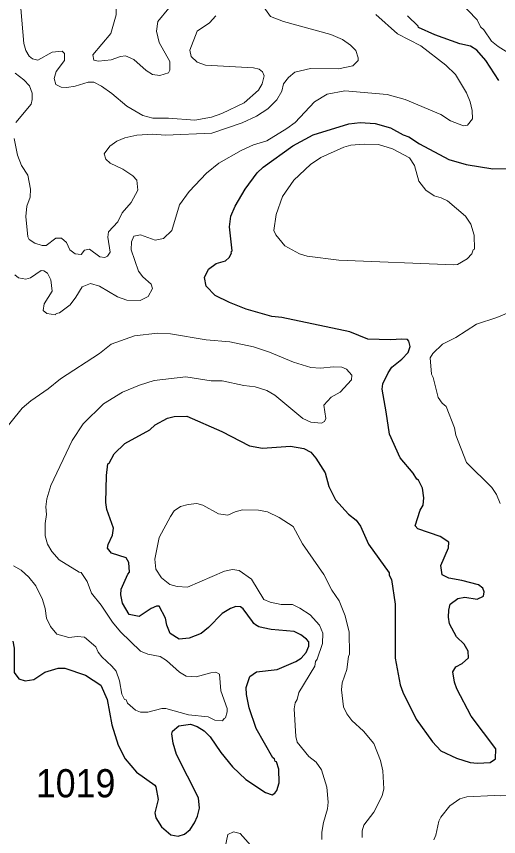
# Model space of a CAD drawing. Extents: x 447.8 to 473.9, y 7733.1 to 7760.8.
# Drawn here: x 462.281 to 463.651, y 7748.146 to 7750.473 of the extents above; entities that cross this region are included whole.
import ezdxf

# ---------------------------------------------------------------- set-up
doc = ezdxf.new("R2010")
doc.units = 0
doc.header["$LTSCALE"] = 0.032
doc.layers.add('1', color=7, linetype='Continuous', lineweight=25)
doc.layers.add('2', color=7, linetype='Continuous', lineweight=13)
doc.layers.add('21', color=7, linetype='Continuous')

msp = doc.modelspace()

# ---------------------------------------------------------------- linework, layer by layer
at = {"layer": '1'}
for points in [[(463.6509, 7750.2912), (463.6143, 7750.3483), (463.5893, 7750.3768), (463.5705, 7750.3882), (463.541, 7750.3949), (463.4695, 7750.4203), (463.4234, 7750.4418), (463.4227, 7750.4453), (463.3923, 7750.4742)], [(462.8155, 7749.732), (462.8269, 7749.756), (462.8487, 7749.7719), (462.8748, 7749.7799), (462.8859, 7749.7895), (462.8919, 7749.8013), (462.8911, 7749.8055), (462.8939, 7749.8083), (462.8861, 7749.8765), (462.8903, 7749.9065), (462.903, 7749.9348), (462.9314, 7749.9825), (462.9652, 7750.0295), (462.9818, 7750.0453), (463.0668, 7750.1061), (463.1241, 7750.137), (463.2251, 7750.1685), (463.258, 7750.1719), (463.3004, 7750.1693), (463.3437, 7750.1574), (463.3794, 7750.1375), (463.3958, 7750.1317), (463.426, 7750.1119), (463.5093, 7750.067), (463.5586, 7750.0526), (463.634, 7750.0404), (463.6953, 7750.0419)], [(463.007, 7749.6218), (462.9334, 7749.643), (462.8862, 7749.6616), (462.8461, 7749.6817), (462.8204, 7749.7076), (462.8155, 7749.732)], [(462.5373, 7749.1711), (462.5412, 7749.2036), (462.5446, 7749.2055), (462.5586, 7749.2326), (462.5892, 7749.2618), (462.6602, 7749.3005), (462.6758, 7749.3147), (462.7107, 7749.3331), (462.729, 7749.3378), (462.7653, 7749.3389), (462.8648, 7749.2951), (462.9436, 7749.2545), (462.9803, 7749.2485), (463.0595, 7749.254), (463.0976, 7749.2476), (463.1174, 7749.2365), (463.1319, 7749.2198), (463.1581, 7749.1786), (463.1683, 7749.1391), (463.1873, 7749.1013), (463.2243, 7749.0607), (463.2461, 7749.0443), (463.2585, 7749.0266), (463.2808, 7748.9763), (463.3396, 7748.8949), (463.34, 7748.8875), (463.3461, 7748.8756), (463.3573, 7748.8059), (463.3573, 7748.6528), (463.3714, 7748.5766), (463.3789, 7748.5558), (463.4165, 7748.4792), (463.4633, 7748.4155), (463.4868, 7748.3901), (463.5308, 7748.3689), (463.5697, 7748.3569), (463.5908, 7748.3547), (463.6263, 7748.357), (463.6419, 7748.367), (463.6426, 7748.3953), (463.5726, 7748.4878), (463.5322, 7748.5651), (463.5251, 7748.584), (463.5211, 7748.6133), (463.529, 7748.628), (463.5468, 7748.6371), (463.5656, 7748.653), (463.5642, 7748.672), (463.5529, 7748.6921), (463.5313, 7748.7127), (463.5114, 7748.7495), (463.5081, 7748.7687), (463.5089, 7748.7883), (463.5132, 7748.8053), (463.5351, 7748.8217), (463.5545, 7748.8251), (463.5895, 7748.8196), (463.6082, 7748.8287), (463.6096, 7748.8403), (463.6057, 7748.8508), (463.5938, 7748.8603), (463.5465, 7748.8732), (463.5095, 7748.8792), (463.4907, 7748.8891), (463.4864, 7748.9157), (463.5085, 7748.9655), (463.5095, 7748.9814), (463.485, 7748.9978), (463.4215, 7749.0196), (463.4139, 7749.0282), (463.4277, 7749.0724), (463.4368, 7749.0863), (463.4383, 7749.107), (463.435, 7749.1346), (463.4229, 7749.1577), (463.4184, 7749.1603), (463.408, 7749.1769), (463.3711, 7749.2209), (463.341, 7749.2883), (463.3316, 7749.351), (463.3197, 7749.4155), (463.322, 7749.4308), (463.3367, 7749.4619), (463.3478, 7749.4783), (463.376, 7749.5003), (463.3939, 7749.5198), (463.3997, 7749.5369), (463.3958, 7749.5522), (463.3922, 7749.5562), (463.3757, 7749.5578), (463.3433, 7749.5555), (463.2791, 7749.5578), (463.2279, 7749.5787), (463.0351, 7749.6187), (463.007, 7749.6218)], [(462.5415, 7748.9753), (462.554, 7749.0012), (462.5574, 7749.021), (462.5386, 7749.0738), (462.535, 7749.0942), (462.5373, 7749.1711)], [(462.331, 7748.5919), (462.3618, 7748.6127), (462.4002, 7748.6239), (462.4192, 7748.6239), (462.4772, 7748.6039), (462.521, 7748.5761), (462.5391, 7748.5354), (462.5527, 7748.4636), (462.5708, 7748.4053), (462.5904, 7748.3669), (462.6221, 7748.3293), (462.6741, 7748.2923), (462.6776, 7748.2873), (462.6839, 7748.252), (462.6745, 7748.2136), (462.6777, 7748.1995), (462.6937, 7748.1744), (462.7201, 7748.1511), (462.7409, 7748.1473), (462.7585, 7748.1535), (462.7748, 7748.1665), (462.7874, 7748.1856), (462.7958, 7748.2047), (462.801, 7748.2273), (462.7983, 7748.2566), (462.736, 7748.3797), (462.7261, 7748.4111), (462.7225, 7748.438), (462.7245, 7748.4458), (462.7423, 7748.461), (462.7758, 7748.4651), (462.7946, 7748.4588), (462.8141, 7748.4466), (462.8319, 7748.4292), (462.8621, 7748.3847), (462.8954, 7748.3445), (462.9328, 7748.3087), (462.989, 7748.2719), (463.0075, 7748.2651), (463.0154, 7748.2693), (463.0209, 7748.277), (463.0278, 7748.2993), (463.0263, 7748.3375), (463.0203, 7748.3586), (463.016, 7748.3596), (463.0141, 7748.3673), (463.0097, 7748.3699), (462.9623, 7748.4529), (462.9421, 7748.5113), (462.935, 7748.5491), (462.9342, 7748.569), (462.944, 7748.6001), (462.9627, 7748.6141), (463.0214, 7748.6202), (463.0744, 7748.6429), (463.0898, 7748.6524), (463.1039, 7748.6687), (463.1117, 7748.6865), (463.1119, 7748.6985), (463.1048, 7748.7063), (463.0893, 7748.719), (463.07, 7748.7282), (463.005, 7748.7338), (462.9821, 7748.7385), (462.9696, 7748.7413), (462.9599, 7748.7474), (462.9556, 7748.7505), (462.9516, 7748.7566), (462.925, 7748.7925), (462.9177, 7748.7979), (462.9049, 7748.7987), (462.8897, 7748.7937), (462.8652, 7748.7794), (462.8264, 7748.7392), (462.8063, 7748.7224), (462.7722, 7748.7097), (462.7439, 7748.7065), (462.7184, 7748.7229), (462.709, 7748.7463), (462.7047, 7748.7662), (462.6869, 7748.8002), (462.6796, 7748.8003), (462.6645, 7748.7937), (462.6295, 7748.7708), (462.6016, 7748.7764), (462.5827, 7748.8083), (462.5782, 7748.8324), (462.5784, 7748.848), (462.5974, 7748.8907), (462.6021, 7748.8961), (462.6006, 7748.9242), (462.5929, 7748.9369), (462.5513, 7748.9502), (462.5399, 7748.965), (462.5415, 7748.9753)], [(462.2714, 7748.7009), (462.2752, 7748.6809), (462.2751, 7748.6115), (462.2881, 7748.5936), (462.3064, 7748.588), (462.331, 7748.5919)]]:
    msp.add_lwpolyline(points, dxfattribs=at)
at = {"layer": '2'}
for points in [[(462.5438, 7750.6136), (462.5633, 7750.5965), (462.5715, 7750.5775), (462.5638, 7750.5147), (462.5651, 7750.4775), (462.5494, 7750.4242)], [(463.727, 7750.3396), (463.6497, 7750.3876), (463.6306, 7750.4029), (463.609, 7750.4347), (463.5995, 7750.443), (463.5898, 7750.4637), (463.5102, 7750.5463)], [(462.8477, 7750.475), (462.8299, 7750.4549), (462.7943, 7750.4309), (462.7739, 7750.3774), (462.778, 7750.3589), (462.7949, 7750.3432), (462.8182, 7750.3343), (462.9549, 7750.3273), (462.9712, 7750.3234), (462.98, 7750.3157), (462.9846, 7750.3041), (462.9794, 7750.2819), (462.9693, 7750.2635), (462.928, 7750.2281), (462.8645, 7750.1972), (462.8353, 7750.1876), (462.7885, 7750.1791), (462.7134, 7750.1846), (462.6692, 7750.1847), (462.6401, 7750.1921), (462.5953, 7750.218), (462.5523, 7750.2546), (462.5231, 7750.2748), (462.5009, 7750.2864), (462.4856, 7750.2867), (462.4486, 7750.2753), (462.4249, 7750.2713), (462.4085, 7750.272), (462.3936, 7750.2799), (462.3883, 7750.2971), (462.3942, 7750.3166), (462.4176, 7750.3478), (462.4177, 7750.3674), (462.4113, 7750.3745), (462.3829, 7750.3715), (462.342, 7750.3489), (462.3273, 7750.3526), (462.318, 7750.3605), (462.3079, 7750.3759), (462.3021, 7750.3964), (462.2912, 7750.5293)], [(462.9844, 7750.4995), (463.0033, 7750.4725), (463.0402, 7750.4587), (463.1742, 7750.422), (463.2076, 7750.4071), (463.2301, 7750.3919), (463.245, 7750.376), (463.2515, 7750.3559), (463.2515, 7750.3477), (463.2371, 7750.3331), (463.1961, 7750.3242), (463.1165, 7750.3257), (463.072, 7750.3145), (463.0541, 7750.2999), (463.04, 7750.282), (463.0355, 7750.2611), (463.0206, 7750.2366), (462.9958, 7750.2112), (462.9636, 7750.1905), (462.9222, 7750.1716), (462.8363, 7750.1414), (462.7043, 7750.1365), (462.6679, 7750.1389), (462.6231, 7750.1365), (462.5891, 7750.1284), (462.567, 7750.1189), (462.5464, 7750.1047), (462.5302, 7750.0835), (462.5353, 7750.068), (462.548, 7750.0571), (462.5833, 7750.0394), (462.6123, 7750.0207), (462.6232, 7750.0085), (462.6263, 7749.9798), (462.6073, 7749.9448), (462.5816, 7749.9156), (462.5694, 7749.8906), (462.543, 7749.862), (462.5406, 7749.8464), (462.5478, 7749.8046), (462.5404, 7749.7929), (462.5322, 7749.7895), (462.5186, 7749.7909), (462.4886, 7749.8126), (462.4744, 7749.8096), (462.4653, 7749.7979), (462.4486, 7749.7996), (462.4327, 7749.8109), (462.4238, 7749.8315), (462.4094, 7749.844), (462.3929, 7749.8439), (462.3662, 7749.8236), (462.3546, 7749.8232), (462.3334, 7749.8297), (462.3173, 7749.8404), (462.3137, 7749.848), (462.3081, 7749.9053), (462.3114, 7749.9351), (462.3202, 7749.9606), (462.3217, 7749.983), (462.3136, 7750.0224), (462.2959, 7750.0503), (462.284, 7750.0791), (462.2753, 7750.1263)], [(462.5494, 7750.4242), (462.4985, 7750.3637), (462.5015, 7750.3492), (462.5142, 7750.3458), (462.5502, 7750.3502), (462.5766, 7750.3593), (462.5914, 7750.3608), (462.6149, 7750.3504), (462.6495, 7750.3192), (462.6679, 7750.3086), (462.6887, 7750.3051), (462.7128, 7750.3132), (462.7175, 7750.3208), (462.7175, 7750.345), (462.687, 7750.3994), (462.6793, 7750.4307), (462.6834, 7750.4587), (462.7141, 7750.4968)], [(462.2771, 7749.7404), (462.2876, 7749.7315), (462.3085, 7749.7278), (462.3212, 7749.7315), (462.3516, 7749.7518), (462.359, 7749.7517), (462.3695, 7749.7447), (462.3794, 7749.7261), (462.3826, 7749.6937), (462.3603, 7749.6575), (462.357, 7749.6384), (462.3675, 7749.6302), (462.3927, 7749.6268), (462.394, 7749.6298), (462.4039, 7749.6324), (462.4336, 7749.6546), (462.4505, 7749.6762), (462.4678, 7749.7062), (462.4917, 7749.7149), (462.5175, 7749.7076), (462.5688, 7749.6779), (462.5949, 7749.6683), (462.6327, 7749.6669), (462.6553, 7749.6783), (462.6677, 7749.7009), (462.6638, 7749.7133), (462.6405, 7749.7344), (462.6285, 7749.7504), (462.6071, 7749.8112), (462.6078, 7749.8332), (462.6145, 7749.8498), (462.634, 7749.8536), (462.6757, 7749.8384), (462.6994, 7749.843), (462.7226, 7749.8655), (462.7444, 7749.9381), (462.7719, 7749.976), (462.8215, 7750.0283), (462.8566, 7750.0566), (462.9194, 7750.0926), (462.9543, 7750.1091), (462.9923, 7750.1204), (463.0497, 7750.1546), (463.0732, 7750.1722), (463.1278, 7750.2309), (463.164, 7750.2525), (463.2136, 7750.2617), (463.334, 7750.2519), (463.3853, 7750.2373), (463.4869, 7750.1944), (463.514, 7750.1768), (463.551, 7750.1623), (463.5622, 7750.1645), (463.5768, 7750.1826), (463.5752, 7750.2062), (463.5698, 7750.2308), (463.5597, 7750.2562), (463.5278, 7750.3084), (463.5011, 7750.3351), (463.4299, 7750.3892), (463.3639, 7750.424), (463.3017, 7750.4787)], [(462.2801, 7750.1725), (462.3233, 7750.2241), (462.3265, 7750.2376), (462.3259, 7750.2552), (462.3184, 7750.276), (462.3027, 7750.2934), (462.2778, 7750.3117)], [(463.6554, 7749.0913), (463.6443, 7749.1169), (463.6312, 7749.1365), (463.5598, 7749.2077), (463.529, 7749.2851), (463.5253, 7749.3056), (463.5017, 7749.3667), (463.4903, 7749.376), (463.4793, 7749.392), (463.4647, 7749.4488), (463.46, 7749.4585), (463.4568, 7749.5046), (463.4635, 7749.5165), (463.4915, 7749.543), (463.529, 7749.5624), (463.588, 7749.5997), (463.6453, 7749.6193), (463.7206, 7749.6505)], [(462.8259, 7748.4863), (462.8448, 7748.4762), (462.8668, 7748.4743), (462.8712, 7748.4817), (462.8753, 7748.4832), (462.8803, 7748.4999), (462.8796, 7748.5093), (462.862, 7748.5603), (462.8582, 7748.6067), (462.8476, 7748.6126), (462.8331, 7748.6111), (462.7919, 7748.5996), (462.7638, 7748.601), (462.7443, 7748.6124), (462.7075, 7748.6462), (462.69, 7748.6574), (462.6542, 7748.6639), (462.6342, 7748.6723), (462.5769, 7748.7271), (462.5539, 7748.7549), (462.5219, 7748.803), (462.4947, 7748.8367), (462.4819, 7748.8703), (462.4648, 7748.8959), (462.4593, 7748.8968), (462.4029, 7748.931), (462.382, 7748.9548), (462.3695, 7748.9763), (462.3634, 7748.9996), (462.3634, 7749.0348), (462.3666, 7749.0605), (462.365, 7749.0814), (462.3682, 7749.1041), (462.3794, 7749.1423), (462.44, 7749.2702), (462.471, 7749.3176), (462.5288, 7749.3736), (462.583, 7749.4071), (462.6305, 7749.4273), (462.6729, 7749.44), (462.7629, 7749.4504), (462.834, 7749.4393), (462.8656, 7749.4392), (462.9273, 7749.4261), (462.9594, 7749.4224), (462.9928, 7749.4122), (463.0148, 7749.3982), (463.0947, 7749.3324), (463.1175, 7749.322), (463.1478, 7749.319), (463.1565, 7749.3243), (463.1601, 7749.3321), (463.154, 7749.3701), (463.1755, 7749.393), (463.2004, 7749.4067), (463.2331, 7749.4419), (463.2339, 7749.4549), (463.2189, 7749.4726), (463.2057, 7749.4784), (463.1819, 7749.4792), (463.1448, 7749.4753), (463.1172, 7749.4771), (463.0678, 7749.4919), (463.0001, 7749.5208), (462.9546, 7749.5354), (462.8873, 7749.5499), (462.8202, 7749.5554), (462.7192, 7749.5722), (462.682, 7749.5746), (462.617, 7749.5667), (462.5508, 7749.5433), (462.5175, 7749.5171), (462.4066, 7749.4448), (462.3716, 7749.4163), (462.3223, 7749.3827), (462.2975, 7749.3613), (462.2393, 7749.2887)], [(463.1488, 7748.1384), (463.149, 7748.1588), (463.1538, 7748.1864), (463.165, 7748.2247), (463.1665, 7748.2439), (463.1633, 7748.2865), (463.1481, 7748.3362), (463.1326, 7748.3578), (463.112, 7748.3731), (463.0785, 7748.414), (463.0752, 7748.4305), (463.0704, 7748.5084), (463.0728, 7748.5257), (463.0783, 7748.5354), (463.0832, 7748.5547), (463.1289, 7748.6295), (463.1304, 7748.643), (463.1354, 7748.6493), (463.1505, 7748.6938), (463.1513, 7748.7231), (463.142, 7748.746), (463.1158, 7748.7756), (463.0864, 7748.7947), (463.0652, 7748.8044), (463.0329, 7748.8052), (463.0017, 7748.8115), (462.984, 7748.8189), (462.9487, 7748.8762), (462.9137, 7748.9013), (462.895, 7748.9037), (462.8726, 7748.8993), (462.7673, 7748.8541), (462.7382, 7748.8557), (462.7169, 7748.8617), (462.6933, 7748.8808), (462.6777, 7748.9054), (462.6748, 7748.9338), (462.6871, 7748.9945), (462.7185, 7749.0544), (462.7298, 7749.0706), (462.7471, 7749.0825), (462.769, 7749.0889), (462.7941, 7749.0912)], [(462.7941, 7749.0912), (462.8105, 7749.0866), (462.8557, 7749.0619), (462.8822, 7749.0578), (462.903, 7749.0678), (462.9232, 7749.0729)], [(462.9232, 7749.0729), (462.9693, 7749.072), (462.9947, 7749.0673), (463.0271, 7749.052), (463.0669, 7749.0257), (463.0938, 7748.9772), (463.1541, 7748.89), (463.1774, 7748.845), (463.1978, 7748.8147), (463.215, 7748.7728), (463.2266, 7748.7258), (463.2274, 7748.6643), (463.224, 7748.6574), (463.2194, 7748.62), (463.2068, 7748.5822), (463.2043, 7748.5625), (463.2106, 7748.5145), (463.2195, 7748.495), (463.2337, 7748.476), (463.2672, 7748.4455), (463.296, 7748.4101), (463.3155, 7748.3621), (463.322, 7748.333), (463.3243, 7748.2814), (463.3197, 7748.2617), (463.2964, 7748.2159), (463.2676, 7748.1791), (463.2628, 7748.163), (463.2628, 7748.1441)], [(462.273, 7748.9145), (462.295, 7748.9017), (462.3171, 7748.8827), (462.3365, 7748.8578), (462.3551, 7748.8194), (462.3633, 7748.7931), (462.367, 7748.7662), (462.3785, 7748.7421), (462.3966, 7748.7206), (462.4304, 7748.7114), (462.4551, 7748.7137), (462.4751, 7748.7122), (462.5071, 7748.6847), (462.5131, 7748.6699), (462.5238, 7748.6562), (462.5527, 7748.6302), (462.5645, 7748.6159), (462.5741, 7748.5883), (462.5811, 7748.5506), (462.5884, 7748.5348), (462.5927, 7748.5339), (462.5967, 7748.5247), (462.6194, 7748.5053), (462.6336, 7748.4998)], [(462.6336, 7748.4998), (462.6543, 7748.499), (462.6945, 7748.51), (462.7057, 7748.5094), (462.7705, 7748.4918), (462.8259, 7748.4863)], [(463.4667, 7748.137), (463.4727, 7748.1503), (463.4808, 7748.1898), (463.4863, 7748.2016), (463.5124, 7748.234), (463.5409, 7748.2536), (463.56, 7748.2593), (463.6387, 7748.2633), (463.6566, 7748.2617), (463.7108, 7748.2681), (463.7331, 7748.2655), (463.7844, 7748.251), (463.8938, 7748.1995), (463.9227, 7748.1789), (463.9603, 7748.1425)], [(462.8732, 7748.1117), (462.882, 7748.1523), (462.8981, 7748.1599), (462.9169, 7748.1551), (462.9691, 7748.0968)]]:
    msp.add_lwpolyline(points, dxfattribs=at)
msp.add_lwpolyline([(463.0368, 7749.9618), (463.069, 7750.0086), (463.1166, 7750.053), (463.1455, 7750.0728), (463.2112, 7750.102), (463.231, 7750.1078), (463.2685, 7750.1109), (463.3099, 7750.1092), (463.3493, 7750.0973), (463.3974, 7750.0717), (463.4117, 7750.0501), (463.4244, 7750.0058), (463.4444, 7749.9798), (463.4677, 7749.9644), (463.4879, 7749.9584), (463.5058, 7749.9494), (463.5567, 7749.906), (463.572, 7749.8835), (463.581, 7749.8522), (463.5819, 7749.8127), (463.5787, 7749.811), (463.5751, 7749.7998), (463.5611, 7749.7853), (463.534, 7749.7696), (463.5231, 7749.7679), (463.1967, 7749.7815), (463.1069, 7749.7928), (463.0851, 7749.7998), (463.0434, 7749.8222), (463.0178, 7749.8538), (463.0127, 7749.8654), (463.0193, 7749.9112)], close=True, dxfattribs=at)

# ---------------------------------------------------------------- texts
at = {"layer": '21', "width": 0.95}
msp.add_text('1019', height=0.08, dxfattribs=at).set_placement((462.3364, 7748.2577))

doc.saveas('drawing.dxf')
